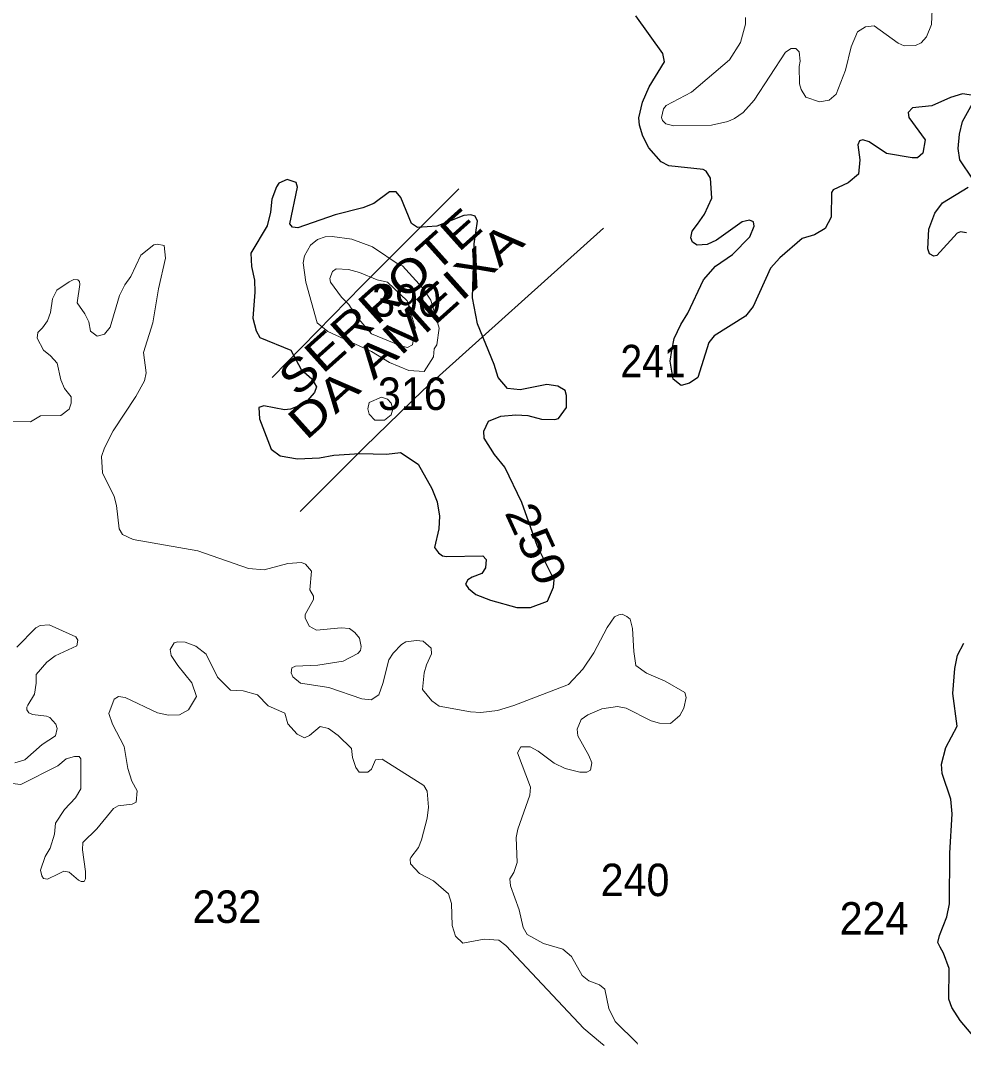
# Model space of a CAD drawing. Extents: x 499.9 to 555.3, y 9281.5 to 9336.8.
# Drawn here: x 524.08 to 528.73, y 9281.5 to 9286.55 of the extents above; entities that cross this region are included whole.
import ezdxf
from ezdxf.enums import TextEntityAlignment as Align

# ---------------------------------------------------------------- set-up
doc = ezdxf.new("R2010")
doc.units = 0
doc.header["$LTSCALE"] = 0.064
for name, color, linetype, lineweight in [('1', 7, 'Continuous', 25), ('2', 7, 'Continuous', 13), ('26', 7, 'Continuous', 25)]:
    doc.layers.add(name, color=color, linetype=linetype, lineweight=lineweight)
doc.layers.add('21', color=7, linetype='Continuous')
doc.layers.add('61', color=7, linetype='Continuous')

msp = doc.modelspace()

# ---------------------------------------------------------------- linework, layer by layer
at = {"layer": '1'}
for points in [[(528.542, 9285.9659), (528.5312, 9285.9001), (528.5056, 9285.8772), (528.4779, 9285.8771), (528.3523, 9285.8991), (528.2663, 9285.9566), (528.2353, 9285.9657), (528.2192, 9285.962), (528.2116, 9285.9419), (528.2208, 9285.8682), (528.2141, 9285.7969), (528.1636, 9285.7543), (528.09, 9285.7191), (528.0818, 9285.7074), (528.079, 9285.5856), (528.0493, 9285.5292), (527.9981, 9285.4982), (527.9361, 9285.4807), (527.8269, 9285.384), (527.7799, 9285.3341), (527.6944, 9285.1455), (527.6579, 9285.0977), (527.5031, 9284.9997), (527.4765, 9284.967), (527.4227, 9284.7946), (527.3813, 9284.7666), (527.34, 9284.7548), (527.3009, 9284.787), (527.2868, 9284.8754), (527.2946, 9284.9275), (527.3061, 9284.9863), (527.3382, 9285.0567), (527.3734, 9285.1115), (527.4495, 9285.2758), (527.5101, 9285.3441), (527.5932, 9285.4005), (527.6779, 9285.4887), (527.7003, 9285.5406), (527.6967, 9285.5621), (527.6775, 9285.5711), (527.6553, 9285.5661), (527.6412, 9285.5621), (527.5151, 9285.4722), (527.468, 9285.4505), (527.4199, 9285.4479), (527.3953, 9285.4626), (527.3877, 9285.483), (527.394, 9285.5155), (527.4208, 9285.5512), (527.4553, 9285.6), (527.4916, 9285.6789), (527.4851, 9285.7771), (527.4637, 9285.8123), (527.448, 9285.8208), (527.2788, 9285.8388), (527.2412, 9285.8575), (527.1813, 9285.9263), (527.1517, 9285.9844), (527.1357, 9286.0385), (527.1324, 9286.074), (527.1492, 9286.1519), (527.1833, 9286.227), (527.2577, 9286.3513), (527.2503, 9286.3913), (527.1172, 9286.5773)], [(528.6681, 9286.1744), (528.5749, 9286.1335), (528.4797, 9286.1235), (528.4588, 9286.1017), (528.4626, 9286.0756), (528.542, 9285.9659)], [(528.7801, 9286.1855), (528.727, 9286.1932), (528.6681, 9286.1744)], [(528.7772, 9285.7725), (528.713, 9285.8674), (528.7056, 9285.9234), (528.7112, 9285.9946), (528.7265, 9286.0563), (528.7839, 9286.1609)], [(526.6809, 9283.6931), (526.7108, 9283.7607), (526.7139, 9283.7982), (526.6325, 9283.9626), (526.5556, 9284.1795), (526.4712, 9284.3534), (526.4204, 9284.4149), (526.3697, 9284.4964), (526.3684, 9284.5303), (526.3909, 9284.5795), (526.452, 9284.6036), (526.5257, 9284.6112), (526.5848, 9284.6082), (526.6525, 9284.5893), (526.7176, 9284.5877), (526.7361, 9284.5936), (526.7753, 9284.6476), (526.7755, 9284.7061), (526.7691, 9284.7307), (526.7328, 9284.7523), (526.6778, 9284.7606), (526.5466, 9284.7342), (526.485, 9284.7403), (526.4386, 9284.7947), (526.4189, 9284.859), (526.3365, 9285.0588), (526.3116, 9285.1883), (526.3208, 9285.4544), (526.3373, 9285.5652), (526.3245, 9285.5899), (526.3044, 9285.5965), (526.2697, 9285.5931), (526.1367, 9285.5414), (526.0405, 9285.5349), (526.012, 9285.5539), (525.9585, 9285.6818), (525.935, 9285.7092), (525.9036, 9285.7097), (525.8255, 9285.6526), (525.7707, 9285.6304), (525.6355, 9285.5964), (525.4518, 9285.5321), (525.4255, 9285.5364), (525.4122, 9285.5517), (525.4497, 9285.7328), (525.4424, 9285.7559), (525.399, 9285.7702), (525.3577, 9285.7519), (525.3453, 9285.7342), (525.323, 9285.6739), (525.3164, 9285.6103), (525.3003, 9285.5427), (525.2194, 9285.4081), (525.2227, 9285.3413), (525.2384, 9285.2743), (525.2399, 9285.2147), (525.229, 9285.0866), (525.2461, 9285.0246), (525.264, 9284.9922), (525.4162, 9284.9296), (525.4671, 9284.8337), (525.5199, 9284.7881), (525.5433, 9284.7493), (525.5341, 9284.7215), (525.4855, 9284.6664), (525.4147, 9284.6387), (525.386, 9284.6357), (525.2838, 9284.6558), (525.2596, 9284.6477), (525.2623, 9284.5909), (525.3204, 9284.441), (525.3633, 9284.4094), (525.4496, 9284.3946), (525.5578, 9284.3996), (525.6287, 9284.4127), (525.7563, 9284.4205), (525.8876, 9284.4175), (525.9564, 9284.4257), (526.044, 9284.3673), (526.1116, 9284.2479), (526.1383, 9284.1822), (526.1501, 9284.1114), (526.1453, 9284.0489), (526.1251, 9283.957), (526.1436, 9283.9299), (526.164, 9283.9162), (526.1845, 9283.9127), (526.3632, 9283.916), (526.3793, 9283.8982), (526.3768, 9283.8572), (526.3581, 9283.8295), (526.3104, 9283.8109), (526.289, 9283.7979), (526.2768, 9283.7765), (526.2916, 9283.7552)], [(528.7462, 9285.5082), (528.7169, 9285.5121), (528.6998, 9285.506), (528.6002, 9285.3955), (528.5853, 9285.3922), (528.5648, 9285.4045), (528.5552, 9285.4297), (528.5615, 9285.5259), (528.5907, 9285.6053), (528.6285, 9285.6552), (528.7544, 9285.7326)], [(526.2916, 9283.7552), (526.3291, 9283.7259), (526.4011, 9283.6982), (526.5298, 9283.6617), (526.5975, 9283.6616), (526.6809, 9283.6931)], [(528.8144, 9281.5084), (528.7148, 9281.6252), (528.6738, 9281.6895), (528.6598, 9281.7301), (528.6615, 9281.882), (528.6331, 9281.9568), (528.6164, 9281.9879), (528.6049, 9282.0094), (528.613, 9282.0452), (528.6503, 9282.136), (528.6632, 9282.2003), (528.6648, 9282.4509), (528.6759, 9282.6448), (528.6696, 9282.716), (528.6269, 9282.8433), (528.6224, 9282.8884), (528.6444, 9282.9706), (528.6996, 9283.0772), (528.6793, 9283.2369), (528.6886, 9283.3602), (528.7017, 9283.4258), (528.733, 9283.4857)]]:
    msp.add_lwpolyline(points, dxfattribs=at)
at = {"layer": '2'}
for points in [[(527.6572, 9286.5692), (527.6574, 9286.5357), (527.6332, 9286.446), (527.5778, 9286.3607), (527.3904, 9286.2007), (527.267, 9286.1355), (527.2531, 9286.1196), (527.2439, 9286.0767), (527.249, 9286.061), (527.2651, 9286.045), (527.3049, 9286.0345), (527.4895, 9286.0378), (527.5705, 9286.057), (527.6034, 9286.0711), (527.6458, 9286.1007), (527.6994, 9286.162), (527.8538, 9286.3976), (527.8818, 9286.4164), (527.9056, 9286.416), (527.9213, 9286.4003), (527.9265, 9286.3535), (527.9217, 9286.328), (527.9235, 9286.2423), (527.9317, 9286.2136), (527.954, 9286.1762), (528.0218, 9286.1541), (528.0691, 9286.1616), (528.1034, 9286.1912), (528.1508, 9286.3098), (528.1782, 9286.425), (528.2089, 9286.4978), (528.2488, 9286.5231), (528.2908, 9286.5276), (528.4096, 9286.4423), (528.439, 9286.4298), (528.4951, 9286.4304), (528.5232, 9286.4436), (528.5499, 9286.4747), (528.574, 9286.535), (528.5805, 9286.6846)], [(525.487, 9283.6097), (525.4867, 9283.6273), (525.5291, 9283.7003), (525.5282, 9283.7179), (525.5106, 9283.749), (525.5183, 9283.8404), (525.4885, 9283.8756), (525.469, 9283.8826), (525.4014, 9283.8779), (525.2853, 9283.8477), (525.2073, 9283.8538), (524.959, 9283.9413), (524.64, 9283.9957), (524.5874, 9284.0213), (524.57, 9284.0498), (524.5571, 9284.1643), (524.5465, 9284.2077), (524.4886, 9284.3243), (524.4841, 9284.4062), (524.4986, 9284.4483), (524.5406, 9284.532), (524.6522, 9284.7016), (524.6954, 9284.7787), (524.7034, 9284.8186), (524.6909, 9284.9181), (524.7369, 9285.0651), (524.7642, 9285.2315), (524.7984, 9285.3835), (524.7921, 9285.4451), (524.7584, 9285.4517), (524.7418, 9285.4485), (524.6778, 9285.3986), (524.6279, 9285.2928), (524.599, 9285.252), (524.5731, 9285.1988), (524.5266, 9285.043), (524.4981, 9285.009), (524.4617, 9284.9989), (524.4298, 9285.023), (524.421, 9285.07), (524.4015, 9285.109), (524.3632, 9285.1624), (524.377, 9285.2527), (524.3744, 9285.2676), (524.3671, 9285.2762), (524.3471, 9285.2774), (524.3248, 9285.2671), (524.264, 9285.2252), (524.2422, 9285.1833), (524.2327, 9285.1146), (524.2182, 9285.0748), (524.1923, 9285.0404), (524.1699, 9285.0172), (524.1661, 9284.988), (524.1971, 9284.9289), (524.2329, 9284.9022), (524.2655, 9284.8661), (524.2831, 9284.7826), (524.3009, 9284.7406), (524.3339, 9284.6989), (524.334, 9284.6691), (524.3244, 9284.6389), (524.2833, 9284.6071), (524.1826, 9284.6062), (524.1344, 9284.577), (524.0393, 9284.5802)], [(527.1255, 9281.5093), (527.1228, 9281.5136), (527.0143, 9281.6201), (526.9844, 9281.6847), (526.9633, 9281.7796), (526.938, 9281.8012), (526.8857, 9281.8217), (526.8529, 9281.8467), (526.8005, 9281.9417), (526.7564, 9281.977), (526.6622, 9282.0052), (526.5816, 9282.0493), (526.5623, 9282.0833), (526.5417, 9282.1708), (526.4991, 9282.2887), (526.4959, 9282.3244), (526.5154, 9282.3557), (526.5322, 9282.4046), (526.5275, 9282.5282), (526.5353, 9282.5689), (526.5944, 9282.7369), (526.5971, 9282.7763), (526.5343, 9282.9445), (526.5498, 9282.9748), (526.596, 9282.9745), (526.635, 9282.9535), (526.7152, 9282.8937), (526.7679, 9282.8683), (526.8409, 9282.8501), (526.8748, 9282.8493), (526.8935, 9282.8602), (526.8994, 9282.8949), (526.8851, 9282.9315), (526.8303, 9283.0292), (526.8283, 9283.0613), (526.8467, 9283.1096), (526.8801, 9283.1326), (526.9501, 9283.1614), (527.0272, 9283.1727), (527.069, 9283.1645), (527.1928, 9283.1028), (527.2334, 9283.0919), (527.287, 9283.0901), (527.3331, 9283.1286), (527.3527, 9283.1649), (527.3644, 9283.2181), (527.3589, 9283.2419), (527.2619, 9283.2982), (527.1689, 9283.3375), (527.117, 9283.376), (527.1065, 9283.4449), (527.1003, 9283.5571), (527.0887, 9283.603), (527.0729, 9283.6177), (527.0495, 9283.6277), (527.0325, 9283.6257), (527.0111, 9283.6146), (526.976, 9283.562), (526.9106, 9283.438), (526.8564, 9283.3573), (526.7851, 9283.2812), (526.5164, 9283.1781), (526.4344, 9283.1536), (526.3532, 9283.1442), (526.3023, 9283.147), (526.1473, 9283.1755), (526.1121, 9283.2015), (526.0661, 9283.2564), (526.0743, 9283.3385), (526.0851, 9283.3781), (526.1103, 9283.4323), (526.1081, 9283.4613), (526.0688, 9283.4949), (526.0366, 9283.4989), (525.9841, 9283.4923), (525.9619, 9283.4793), (525.9206, 9283.4365), (525.8989, 9283.4035), (525.8701, 9283.2859), (525.8499, 9283.2314), (525.8126, 9283.2069), (525.7667, 9283.2104), (525.6043, 9283.2666), (525.465, 9283.2889), (525.4263, 9283.3193), (525.4191, 9283.3399), (525.4212, 9283.3642), (525.4404, 9283.3719), (525.5502, 9283.3766), (525.6751, 9283.396), (525.7465, 9283.4343), (525.7603, 9283.4489), (525.7633, 9283.469), (525.7547, 9283.5097), (525.7326, 9283.5376)], [(524.0668, 9283.4653), (524.1604, 9283.5605), (524.1808, 9283.5722), (524.2257, 9283.5766), (524.3572, 9283.517), (524.3672, 9283.5009), (524.3617, 9283.4717), (524.2547, 9283.4226), (524.215, 9283.3924), (524.1618, 9283.3307), (524.1623, 9283.2889), (524.1527, 9283.2349), (524.1203, 9283.1802), (524.1163, 9283.1707), (524.1156, 9283.1561), (524.1257, 9283.1422), (524.1435, 9283.1332), (524.2132, 9283.1265), (524.2297, 9283.1195), (524.259, 9283.0867), (524.2646, 9283.0651), (524.2574, 9283.0282), (524.1911, 9282.9865), (524.1057, 9282.9109), (524.0566, 9282.8955)], [(525.7326, 9283.5376), (525.7061, 9283.5576), (525.6648, 9283.561), (525.5425, 9283.55), (525.507, 9283.5699), (525.487, 9283.6097)], [(524.0157, 9282.7963), (524.0867, 9282.7896), (524.2683, 9282.8812), (524.3089, 9282.9147), (524.3502, 9282.9275), (524.3742, 9282.9261), (524.3814, 9282.9161), (524.3817, 9282.7672), (524.3548, 9282.7224), (524.3009, 9282.665), (524.2566, 9282.5981), (524.2514, 9282.5442), (524.2308, 9282.4743), (524.2063, 9282.4341), (524.1835, 9282.3659), (524.1895, 9282.3393), (524.1981, 9282.3252), (524.2176, 9282.3217), (524.2725, 9282.3487), (524.2972, 9282.3615), (524.3239, 9282.3575), (524.3703, 9282.3172), (524.3841, 9282.3107), (524.3974, 9282.3109), (524.4048, 9282.3241), (524.4042, 9282.3603), (524.3901, 9282.4669), (524.3924, 9282.5023), (524.4605, 9282.5703), (524.5424, 9282.6707), (524.5663, 9282.6844), (524.6341, 9282.6926), (524.654, 9282.7026), (524.6586, 9282.7573), (524.6335, 9282.8052), (524.6141, 9282.8678), (524.5955, 9282.9762), (524.5378, 9283.086), (524.5194, 9283.1386), (524.5462, 9283.2102), (524.5674, 9283.2219), (524.6004, 9283.2181), (524.7601, 9283.1429), (524.813, 9283.1303), (524.8682, 9283.1315), (524.9124, 9283.1574), (524.9514, 9283.2232), (524.929, 9283.2895), (524.8591, 9283.3756), (524.8268, 9283.4255), (524.8216, 9283.4544), (524.8417, 9283.4868), (524.8587, 9283.4926), (524.8964, 9283.4904), (524.9486, 9283.4703), (524.9994, 9283.432), (525.0549, 9283.3184), (525.1198, 9283.2541), (525.1818, 9283.2505), (525.2529, 9283.2307), (525.3047, 9283.1765), (525.3871, 9283.1411), (525.4013, 9283.0879), (525.4475, 9283.0372), (525.4844, 9283.0195), (525.5087, 9283.0297), (525.5606, 9283.0753), (525.6019, 9283.0656)], [(525.6019, 9283.0656), (525.6505, 9283.0307), (525.7155, 9282.9656), (525.7208, 9282.9222), (525.7368, 9282.8725), (525.7536, 9282.8504)], [(525.7536, 9282.8504), (525.7958, 9282.8503), (525.8146, 9282.8647), (525.834, 9282.9097), (525.8668, 9282.913), (526.0715, 9282.7847), (526.0878, 9282.7565), (526.0944, 9282.677), (526.0882, 9282.6237), (526.0613, 9282.5162), (526.0459, 9282.4786), (526.0082, 9282.4293), (526.0052, 9282.4212), (526.0056, 9282.3983), (526.0501, 9282.3508), (526.1193, 9282.3137), (526.1931, 9282.2495), (526.2091, 9282.2027), (526.211, 9282.0946), (526.2284, 9282.0419), (526.2642, 9282.0064), (526.3691, 9282.0268), (526.4411, 9282.0215), (526.4765, 9281.995), (526.8608, 9281.5855), (526.9429, 9281.5176), (526.9612, 9281.5025)]]:
    msp.add_lwpolyline(points, dxfattribs=at)
for points in [[(526.1474, 9285.0372), (526.1062, 9285.1764), (526.0663, 9285.2372), (525.9665, 9285.3447), (525.9552, 9285.347), (525.8192, 9285.439), (525.7175, 9285.4769), (525.6196, 9285.4901), (525.5859, 9285.4879), (525.5487, 9285.4743), (525.5142, 9285.4475), (525.4838, 9285.3937), (525.4771, 9285.3605), (525.4901, 9285.2641), (525.5471, 9285.0642), (525.5994, 9285.0213), (525.8144, 9284.9235), (525.9036, 9284.8694), (525.9982, 9284.8296), (526.0741, 9284.8252), (526.1198, 9284.8968), (526.1231, 9284.9365), (526.1357, 9284.9564)], [(526.0293, 9285.0419), (525.9896, 9285.1732), (525.8931, 9285.2651), (525.8422, 9285.2758), (525.7546, 9285.3131), (525.7006, 9285.3275), (525.6408, 9285.3309), (525.6225, 9285.317), (525.6095, 9285.2824), (525.6114, 9285.2652), (525.6667, 9285.191), (525.7018, 9285.1551), (525.7399, 9285.0955), (525.8139, 9285.0105), (525.9538, 9284.9521), (525.9918, 9284.9431), (526.0164, 9284.9564)], [(525.8784, 9284.5849), (525.9112, 9284.6102), (525.9191, 9284.638), (525.9109, 9284.6679), (525.8937, 9284.6879), (525.8635, 9284.6974), (525.8033, 9284.6719), (525.7968, 9284.6411), (525.802, 9284.6144), (525.8312, 9284.5853)]]:
    msp.add_lwpolyline(points, close=True, dxfattribs=at)
at = {"layer": '26'}
for points in [[(525.3251, 9284.7942), (525.7676, 9285.2481), (526.2444, 9285.7249)], [(525.4624, 9284.1343), (525.779, 9284.4509), (526.0689, 9284.7332), (526.9577, 9285.5304)]]:
    msp.add_lwpolyline(points, dxfattribs=at)

# ---------------------------------------------------------------- texts
at = {"layer": '21'}
for s, width, p in [('390', 0.95, (525.8172, 9285.0946)), ('241', 0.9, (527.0411, 9284.7958)), ('316', 0.95, (525.8459, 9284.6349)), ('240', 0.95, (526.9434, 9282.2387)), ('232', 0.95, (524.9322, 9282.1066)), ('224', 0.95, (528.1214, 9282.0491))]:
    msp.add_text(s, height=0.16, dxfattribs=dict(at, width=width)).set_placement(p)
at = {"layer": '26'}
for s, width, p in [('SERROTE', 1.2, (525.9085, 9285.1086)), ('DA AMEIXA', 1.25, (526.0353, 9284.9672))]:
    msp.add_text(s, height=0.16, rotation=41.857, dxfattribs=dict(at, width=width)).set_placement(p, align=Align.CENTER)
at = {"layer": '61', "width": 1.15}
msp.add_text('250', height=0.16, rotation=294.624, dxfattribs=at).set_placement((526.5537, 9283.9425), align=Align.CENTER)

doc.saveas('drawing.dxf')
